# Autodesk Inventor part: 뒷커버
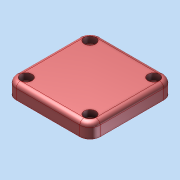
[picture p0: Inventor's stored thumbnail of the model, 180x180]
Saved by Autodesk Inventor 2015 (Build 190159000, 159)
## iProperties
Created: 2026-02
Part Number: 뒷커버
Material: 일반
Document SubType Name: Modeling
Designer: Administrator
Density: 1 g/cm^3
Appearance: 기본값
Author: Administrator
Author: jhkim
Creation Date: 2026-01-30
Sending System: Autodesk Inventor 2026
Preprocessor: ST-DEVELOPER v20.1
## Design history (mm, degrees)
node "뒷커버1"
node "솔리드1"
node "기준1"
